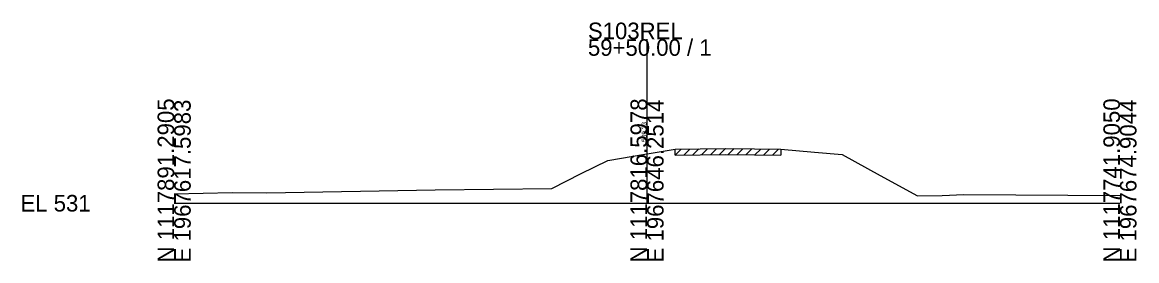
# Model space of a CAD drawing. Extents: x -26 to 163, y -10 to 24518.
# Drawn here: x -25.7 to 162.8, y 10490.3 to 10530.5 of the extents above; entities that cross this region are included whole.
import ezdxf

# ---------------------------------------------------------------- set-up
doc = ezdxf.new("R2010")
doc.units = 0
for name, color, linetype in [('RD_GPK_XS_Cell', 7, 'Continuous'), ('RD_XS_ExGround', 7, 'Continuous'), ('RD_XS_ExPaveRet', 7, 'Continuous'), ('RD_XS_TX_Elev_EX', 7, 'Continuous')]:
    doc.layers.add(name, color=color, linetype=linetype)

msp = doc.modelspace()

# ---------------------------------------------------------------- linework, layer by layer
at = {"layer": 'RD_GPK_XS_Cell'}
for p, q in [((80, 10500), (80, 10527.68)), ((0, 10500), (80, 10500)), ((80, 10500), (160, 10500))]:
    msp.add_line(p, q, dxfattribs=at)
at = {"layer": 'RD_XS_ExGround'}
msp.add_lwpolyline([(0, 10501.61), (9.79, 10501.82), (15.65, 10501.78), (44.14, 10502.25), (63.9, 10502.51), (68.85, 10504.99), (73.34, 10507.22), (79.61, 10508.27), (80, 10508.33), (84.73, 10509.1), (89, 10509.16), (93.32, 10509.23), (98.19, 10509.16), (102.66, 10509.11), (108.32, 10508.59), (113.02, 10508.2), (119.43, 10504.68), (125.74, 10501.23), (129.94, 10501.31), (133.57, 10501.49), (160, 10501.33)], dxfattribs=at)
at = {"layer": 'RD_XS_ExPaveRet'}
for p, q in [((84.73, 10508.1), (85.75, 10509.12)), ((84.73, 10508.1), (84.73, 10509.1)), ((86.23, 10508.12), (87.25, 10509.14)), ((87.73, 10508.15), (88.75, 10509.16)), ((89.23, 10508.17), (90.25, 10509.18)), ((90.73, 10508.19), (91.75, 10509.2)), ((92.23, 10508.21), (93.25, 10509.23)), ((93.74, 10508.22), (94.72, 10509.21)), ((95.24, 10508.2), (96.22, 10509.19)), ((96.74, 10508.18), (97.72, 10509.17)), ((98.24, 10508.16), (99.23, 10509.15)), ((99.74, 10508.14), (100.73, 10509.13)), ((101.24, 10508.13), (102.23, 10509.12)), ((102.66, 10509.11), (102.66, 10508.11)), ((84.73, 10508.1), (89, 10508.16)), ((89, 10508.16), (93.32, 10508.23)), ((93.32, 10508.23), (98.19, 10508.16)), ((98.19, 10508.16), (102.66, 10508.11))]:
    msp.add_line(p, q, dxfattribs=at)

# ---------------------------------------------------------------- texts
at = {"layer": 'RD_GPK_XS_Cell'}
for s, p in [('S103REL', (70, 10527.68)), ('59+50.00 / 1', (70, 10524.88)), ('EL 531', (-26, 10498.6))]:
    msp.add_text(s, height=2.8, dxfattribs=at).set_placement(p)
for s, p in [('N 1117891.2905', (0, 10490)), ('E 1967617.5983', (2.8, 10490)), ('N 1117816.5978', (80, 10490)), ('E 1967646.2514', (82.8, 10490)), ('N 1117741.9050', (160, 10490)), ('E 1967674.9044', (162.8, 10490))]:
    msp.add_text(s, height=2.8, rotation=90, dxfattribs=at).set_placement(p)
at = {"layer": 'RD_XS_TX_Elev_EX'}
msp.add_text('539.33', height=0.8, rotation=90, dxfattribs=at).set_placement((79.9, 10510.33))

doc.saveas('drawing.dxf')
